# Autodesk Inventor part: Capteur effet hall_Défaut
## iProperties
Shininess: 64.0
Length Units: 11269
Angle Units: 11279
Time Units: 11290
Mass Units: 11283
Length Display Precision: 3
Angle Display Precision: 2
Compacted: True
Part Number: Capteur effet hall_Défaut
Document SubType Name: Modeling
Created: 2006-01
Material: Par défaut
Designer: riri
Density: 0.0
Volumn: 0.0
Area: 0.0
PropertySet Name: Model Information
Control State: 0
Master: False
Checked Out: False
Author: riri
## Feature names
1. Base1
